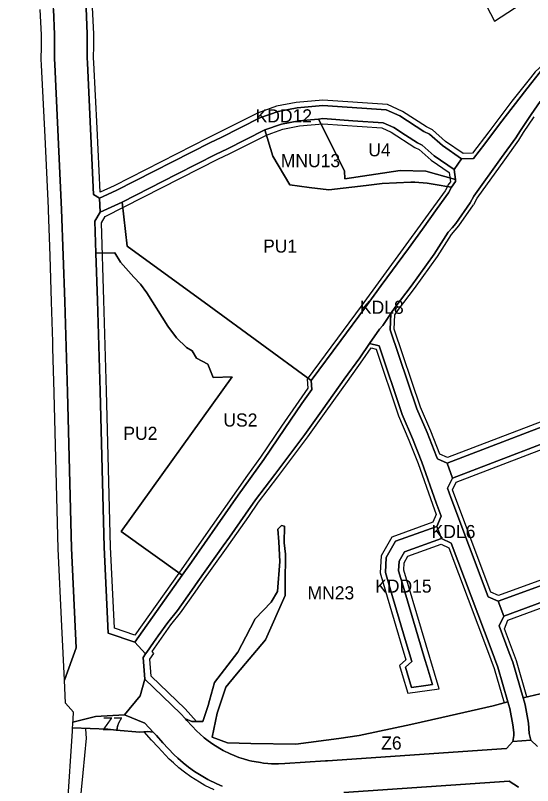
# Model space of a CAD drawing. Extents: x 7440055 to 7442242, y 5549003 to 5552256.
# Drawn here: x 7440536 to 7440932, y 5550092 to 5550680 of the extents above; entities that cross this region are included whole.
import ezdxf

# ---------------------------------------------------------------- set-up
doc = ezdxf.new("R2010")
doc.units = 0
for name, color, linetype in [('linie_rozgraniczajace', 7, 'Continuous'), ('linie_zabudowy_nieprzekraczalne', 7, 'Continuous'), ('oznaczenia_przeznaczen', 7, 'Continuous')]:
    doc.layers.add(name, color=color, linetype=linetype)

msp = doc.modelspace()

# ---------------------------------------------------------------- linework, layer by layer
at = {"layer": 'linie_rozgraniczajace'}
for points in [[(7440573.92, 5550172.69), (7440582.76, 5550197.27), (7440579.13, 5550273.35), (7440576.06, 5550392.67), (7440574.03, 5550461.9), (7440571.71, 5550531.98), (7440566.39, 5550642.67), (7440566.17, 5550647.16), (7440566.21, 5550665.57), (7440565.4, 5550685.1), (7440564.29, 5550711.77), (7440563.86, 5550722.35), (7440563.39, 5550733.5), (7440562.57, 5550746.25), (7440561.03, 5550769.99), (7440559.99, 5550785.92), (7440559.23, 5550801.45), (7440557.17, 5550854.15), (7440555.49, 5550871.65), (7440553.94, 5550886.18), (7440551.79, 5550907.38), (7440536.34, 5551228.21)], [(7440565.4, 5550685.1), (7440566.21, 5550665.57), (7440566.17, 5550647.16), (7440566.39, 5550642.67), (7440571.71, 5550531.98), (7440574.03, 5550461.9), (7440576.06, 5550392.67), (7440579.13, 5550273.35), (7440582.76, 5550197.27), (7440573.92, 5550172.69), (7440571.95, 5550214.02), (7440569.14, 5550272.98), (7440567.61, 5550332.35), (7440566.08, 5550391.72), (7440566.07, 5550392.39), (7440565.57, 5550409.22), (7440565.08, 5550426.06), (7440564.93, 5550431), (7440564.48, 5550446.3), (7440564.04, 5550461.59), (7440562.88, 5550496.59), (7440561.72, 5550531.58), (7440561.68, 5550532.37), (7440561.65, 5550533.16), (7440559.02, 5550587.67), (7440556.4, 5550642.19), (7440556.17, 5550646.93), (7440556.19, 5550656.15), (7440556.21, 5550665.37), (7440555.81, 5550675.03), (7440555.41, 5550684.69)], [(7440591.17, 5550647.75), (7440591.21, 5550666.06), (7440590.37, 5550686.14)], [(7440590.37, 5550686.14), (7440591.21, 5550666.06), (7440591.17, 5550647.75), (7440591.36, 5550643.88), (7440596.18, 5550543.57), (7440600.55, 5550540.64), (7440601.18, 5550529.91), (7440597.01, 5550523.23), (7440597.82, 5550498.78), (7440599.02, 5550462.68), (7440601.05, 5550393.36), (7440604.12, 5550274.26), (7440607.24, 5550208.62), (7440627.64, 5550201.8)], [(7440986.37, 5550682.63), (7440974.26, 5550670.64), (7440962.15, 5550658.65), (7440956.69, 5550654.35), (7440937.69, 5550637.36), (7440927.23, 5550624.19), (7440906.38, 5550597.1), (7440895.14, 5550582.1), (7440886.56, 5550571.01), (7440877.43, 5550570.75), (7440862.74, 5550580.86)], [(7440862.74, 5550580.86), (7440852.97, 5550589.55), (7440848.72, 5550591.65), (7440830.36, 5550603.47), (7440819.92, 5550608.19), (7440771.31, 5550611.47), (7440751.66, 5550609.72), (7440737.13, 5550606.98), (7440723.1, 5550602), (7440693.63, 5550587.11), (7440685.39, 5550583.26), (7440613.51, 5550546.64), (7440600.55, 5550540.64), (7440596.18, 5550543.57), (7440591.36, 5550643.88), (7440591.17, 5550647.75)], [(7440937.54, 5550614.43), (7440930.55, 5550604.54), (7440922.38, 5550592.41), (7440918.8, 5550586.69), (7440908.08, 5550571.82), (7440886.74, 5550542.25), (7440884.12, 5550537.22), (7440873.09, 5550521.44), (7440870.18, 5550518.07), (7440867.28, 5550514.71), (7440861.92, 5550506.27), (7440856.56, 5550497.84), (7440839.01, 5550473.46), (7440826.72, 5550457.37), (7440823.48, 5550452.67), (7440820.24, 5550447.97), (7440817.21, 5550443.41), (7440814.64, 5550440.77), (7440807.11, 5550429.83), (7440799.57, 5550418.9), (7440787.7, 5550402.48), (7440771.56, 5550379.89), (7440757.55, 5550360.16), (7440734.69, 5550329.81), (7440719.81, 5550310.29), (7440712.34, 5550299.45), (7440700.08, 5550281.97), (7440695.3, 5550275.32), (7440675.91, 5550248.1), (7440671.21, 5550241.5), (7440660.27, 5550225.91), (7440652.87, 5550216.76), (7440645.58, 5550206.45), (7440642.03, 5550201.42), (7440636.81, 5550194.03), (7440635.83, 5550192.65), (7440627.64, 5550201.8), (7440663.84, 5550252.75), (7440670.88, 5550262.67), (7440690.93, 5550291.4), (7440706.55, 5550313.81), (7440726.16, 5550341.14), (7440742.22, 5550364.95), (7440755.44, 5550383.92), (7440762.98, 5550394.73), (7440762.57, 5550401.52), (7440785.26, 5550431.95), (7440803.21, 5550456.45), (7440816.04, 5550473.95), (7440836.83, 5550502.27), (7440847.53, 5550516.98), (7440858.83, 5550532.84), (7440867.39, 5550544.81), (7440869.62, 5550549.11), (7440872.9, 5550553.35), (7440872.68, 5550555.07), (7440871.76, 5550562.52), (7440877.43, 5550570.75), (7440886.56, 5550571.01), (7440895.14, 5550582.1), (7440906.38, 5550597.1), (7440927.23, 5550624.19), (7440937.69, 5550637.36)], [(7440970.15, 5550377.98), (7440866.42, 5550338.29), (7440858.96, 5550341.75), (7440858.37, 5550343.45), (7440851.07, 5550361.74), (7440843.18, 5550379.93), (7440822.89, 5550440.17), (7440823.48, 5550452.67), (7440826.72, 5550457.37), (7440839.01, 5550473.46), (7440856.56, 5550497.84), (7440861.92, 5550506.27), (7440867.28, 5550514.71), (7440870.18, 5550518.07), (7440873.09, 5550521.44), (7440884.12, 5550537.22), (7440886.74, 5550542.25), (7440908.08, 5550571.82), (7440918.8, 5550586.69), (7440922.38, 5550592.41), (7440930.55, 5550604.54), (7440937.54, 5550614.43)], [(7440974.34, 5550366.74), (7440870.42, 5550326.97), (7440866.42, 5550338.29), (7440970.15, 5550377.98)], [(7440990.2, 5550263.91), (7440905.47, 5550232.9), (7440897.83, 5550236.24), (7440869.31, 5550312.08), (7440866.77, 5550319.38), (7440870.42, 5550326.97), (7440974.34, 5550366.74)], [(7440993.91, 5550252.48), (7440909.66, 5550221.66), (7440905.47, 5550232.9), (7440990.2, 5550263.91)], [(7440963.57, 5550168.27), (7440924.49, 5550159.2), (7440916.62, 5550186.44), (7440913.94, 5550193.48), (7440911.25, 5550200.53), (7440908.69, 5550207.34), (7440906.13, 5550214.15), (7440909.66, 5550221.66), (7440993.91, 5550252.48)], [(7440627.64, 5550201.8), (7440635.83, 5550192.65), (7440634.02, 5550190.08), (7440635.27, 5550173.32), (7440631.62, 5550160.64), (7440619.71, 5550146.25), (7440597.47, 5550145.03), (7440580.34, 5550140.54), (7440580.41, 5550141.53), (7440580.44, 5550142.16), (7440580.48, 5550142.79), (7440580.75, 5550148.12), (7440574.76, 5550155.07), (7440573.92, 5550172.69)], [(7440619.71, 5550146.25), (7440631.62, 5550160.64), (7440635.27, 5550173.32), (7440662.55, 5550147.18), (7440666.34, 5550143.04), (7440667.5, 5550141.78), (7440675.08, 5550133.7), (7440677.25, 5550131.67), (7440680.56, 5550128.75), (7440683.63, 5550126.33), (7440687.22, 5550123.79), (7440692.54, 5550120.46), (7440695.13, 5550118.97), (7440700.65, 5550116.38), (7440703.72, 5550115.04), (7440707.28, 5550113.71), (7440710.71, 5550112.58), (7440714.78, 5550111.45), (7440717.2, 5550110.87), (7440718.99, 5550110.48), (7440723.67, 5550109.67), (7440726.09, 5550109.35), (7440729.33, 5550109.05), (7440732.07, 5550108.87), (7440734.89, 5550108.78), (7440736.16, 5550108.77), (7440737.55, 5550108.79), (7440742.45, 5550108.99), (7440773.52, 5550111.1), (7440774.9, 5550111.19), (7440911.77, 5550120.46), (7440916.54, 5550125.84), (7440930.37, 5550126.73), (7440935.61, 5550122.08)], [(7440935.61, 5550122.08), (7440930.37, 5550126.73), (7440929.08, 5550132.04), (7440928.67, 5550139.92), (7440926.01, 5550153.93), (7440925.25, 5550156.57), (7440924.49, 5550159.2), (7440963.57, 5550168.27)], [(7440694.35, 5550091.85), (7440690.35, 5550093.6), (7440683.54, 5550096.79), (7440679.65, 5550099.04), (7440673.36, 5550102.97), (7440668.64, 5550106.31), (7440664.55, 5550109.55), (7440660.45, 5550113.16), (7440657.41, 5550116), (7440649.16, 5550124.78), (7440644.1, 5550130.31), (7440641.77, 5550132.87), (7440635.4, 5550139.84), (7440619.71, 5550146.25)], [(7440576.17, 5550076.23), (7440579.91, 5550133.83), (7440580.07, 5550136.34), (7440593.51, 5550135.79), (7440606.94, 5550135.23), (7440613.49, 5550134.57), (7440631.45, 5550132.87), (7440637.67, 5550133.41), (7440641.77, 5550132.87), (7440644.1, 5550130.31), (7440649.16, 5550124.78), (7440657.41, 5550116), (7440660.45, 5550113.16), (7440664.55, 5550109.55), (7440668.64, 5550106.31), (7440673.36, 5550102.97), (7440679.65, 5550099.04), (7440683.54, 5550096.79), (7440690.35, 5550093.6), (7440694.35, 5550091.85)], [(7440787.47, 5550086.98), (7440913.88, 5550095.55), (7440921.08, 5550091.06)], [(7440921.08, 5550091.06), (7440913.88, 5550095.55), (7440787.47, 5550086.98)]]:
    msp.add_lwpolyline(points, dxfattribs=at)
for points in [[(7440600.55, 5550540.64), (7440613.51, 5550546.64), (7440685.39, 5550583.26), (7440693.63, 5550587.11), (7440723.1, 5550602), (7440737.13, 5550606.98), (7440751.66, 5550609.72), (7440771.31, 5550611.47), (7440819.92, 5550608.19), (7440830.36, 5550603.47), (7440848.72, 5550591.65), (7440852.97, 5550589.55), (7440862.74, 5550580.86), (7440877.43, 5550570.75), (7440871.76, 5550562.52), (7440856.56, 5550572.98), (7440847.34, 5550581.18), (7440843.78, 5550582.93), (7440834.68, 5550588.8), (7440825.57, 5550594.67), (7440817.45, 5550598.33), (7440794.43, 5550599.89), (7440771.42, 5550601.45), (7440768.04, 5550601.14), (7440753.03, 5550599.8), (7440739.74, 5550597.3), (7440727.04, 5550592.79), (7440698, 5550578.12), (7440689.78, 5550574.27), (7440659.67, 5550558.93), (7440638.78, 5550548.29), (7440617.88, 5550537.64), (7440601.18, 5550529.91)], [(7440727.04, 5550592.79), (7440739.74, 5550597.3), (7440753.03, 5550599.8), (7440768.04, 5550601.14), (7440787.86, 5550561.53), (7440788.19, 5550555.47), (7440830.54, 5550561.81), (7440850.23, 5550561.22), (7440872.68, 5550555.07), (7440872.9, 5550553.35), (7440869.62, 5550549.11), (7440864.72, 5550549.93), (7440861.91, 5550550.4), (7440851.2, 5550552.18), (7440841.72, 5550553), (7440838.73, 5550552.97), (7440816.74, 5550552.01), (7440804.39, 5550550.42), (7440775.87, 5550546.97), (7440761.04, 5550548.96), (7440746.2, 5550550.95), (7440733.16, 5550572.76)], [(7440768.04, 5550601.14), (7440771.42, 5550601.45), (7440794.43, 5550599.89), (7440817.45, 5550598.33), (7440825.57, 5550594.67), (7440834.68, 5550588.8), (7440843.78, 5550582.93), (7440847.34, 5550581.18), (7440856.56, 5550572.98), (7440871.76, 5550562.52), (7440872.68, 5550555.07), (7440850.23, 5550561.22), (7440830.54, 5550561.81), (7440788.19, 5550555.47), (7440787.86, 5550561.53)], [(7440617.88, 5550537.64), (7440638.78, 5550548.29), (7440659.67, 5550558.93), (7440689.78, 5550574.27), (7440698, 5550578.12), (7440727.04, 5550592.79), (7440733.16, 5550572.76), (7440746.2, 5550550.95), (7440761.04, 5550548.96), (7440775.87, 5550546.97), (7440804.39, 5550550.42), (7440816.74, 5550552.01), (7440838.73, 5550552.97), (7440841.72, 5550553), (7440851.2, 5550552.18), (7440861.91, 5550550.4), (7440864.72, 5550549.93), (7440869.62, 5550549.11), (7440867.39, 5550544.81), (7440858.83, 5550532.84), (7440847.53, 5550516.98), (7440836.83, 5550502.27), (7440816.04, 5550473.95), (7440803.21, 5550456.45), (7440785.26, 5550431.95), (7440762.57, 5550401.52), (7440684.59, 5550458.38), (7440621.76, 5550504.17)], [(7440597.82, 5550498.78), (7440597.01, 5550523.23), (7440601.18, 5550529.91), (7440617.88, 5550537.64), (7440621.76, 5550504.17), (7440684.59, 5550458.38), (7440762.57, 5550401.52), (7440762.98, 5550394.73), (7440755.44, 5550383.92), (7440742.22, 5550364.95), (7440726.16, 5550341.14), (7440706.55, 5550313.81), (7440690.93, 5550291.4), (7440670.88, 5550262.67), (7440663.84, 5550252.75), (7440617.15, 5550286.17), (7440702.17, 5550404.37), (7440687.65, 5550403.78), (7440683.48, 5550413.89), (7440674.73, 5550418.57), (7440671.55, 5550424.11), (7440667.22, 5550426.69), (7440659.56, 5550433.94), (7440652.96, 5550443.02), (7440636.9, 5550468.37), (7440631.99, 5550474.94), (7440626.95, 5550480.51), (7440616.66, 5550491.91), (7440612.32, 5550499.03)], [(7440604.12, 5550274.26), (7440601.05, 5550393.36), (7440599.02, 5550462.68), (7440597.82, 5550498.78), (7440612.32, 5550499.03), (7440616.66, 5550491.91), (7440626.95, 5550480.51), (7440631.99, 5550474.94), (7440636.9, 5550468.37), (7440652.96, 5550443.02), (7440659.56, 5550433.94), (7440667.22, 5550426.69), (7440671.55, 5550424.11), (7440674.73, 5550418.57), (7440683.48, 5550413.89), (7440687.65, 5550403.78), (7440702.17, 5550404.37), (7440617.15, 5550286.17), (7440663.84, 5550252.75), (7440627.64, 5550201.8), (7440607.24, 5550208.62)], [(7440807.11, 5550429.83), (7440814.64, 5550440.77), (7440817.21, 5550443.41), (7440820.24, 5550447.97), (7440823.48, 5550452.67), (7440822.89, 5550440.17), (7440843.18, 5550379.93), (7440851.07, 5550361.74), (7440858.37, 5550343.45), (7440858.96, 5550341.75), (7440866.42, 5550338.29), (7440870.42, 5550326.97), (7440866.77, 5550319.38), (7440869.31, 5550312.08), (7440897.83, 5550236.24), (7440905.47, 5550232.9), (7440909.66, 5550221.66), (7440906.13, 5550214.15), (7440908.69, 5550207.34), (7440911.25, 5550200.53), (7440913.94, 5550193.48), (7440916.62, 5550186.44), (7440924.49, 5550159.2), (7440925.25, 5550156.57), (7440926.01, 5550153.93), (7440928.67, 5550139.92), (7440929.08, 5550132.04), (7440930.37, 5550126.73), (7440916.54, 5550125.84), (7440917.42, 5550130.49), (7440917.41, 5550132.69), (7440916.7, 5550138.65), (7440914.33, 5550151.14), (7440912.91, 5550156.03), (7440905.23, 5550182.63), (7440900.03, 5550196.28), (7440869.6, 5550277.23), (7440862.08, 5550280.74), (7440858.49, 5550290.07), (7440861.88, 5550297.77), (7440858.03, 5550307.99), (7440847.13, 5550339.24), (7440839.99, 5550357.13), (7440831.97, 5550375.62), (7440814.43, 5550427.93)], [(7440634.02, 5550190.08), (7440635.83, 5550192.65), (7440636.81, 5550194.03), (7440642.03, 5550201.42), (7440645.58, 5550206.45), (7440652.87, 5550216.76), (7440660.27, 5550225.91), (7440671.21, 5550241.5), (7440675.91, 5550248.1), (7440695.3, 5550275.32), (7440700.08, 5550281.97), (7440712.34, 5550299.45), (7440719.81, 5550310.29), (7440734.69, 5550329.81), (7440757.55, 5550360.16), (7440771.56, 5550379.89), (7440787.7, 5550402.48), (7440799.57, 5550418.9), (7440807.11, 5550429.83), (7440814.43, 5550427.93), (7440831.97, 5550375.62), (7440839.99, 5550357.13), (7440847.13, 5550339.24), (7440858.03, 5550307.99), (7440861.88, 5550297.77), (7440858.49, 5550290.07), (7440826.87, 5550278.7), (7440819.81, 5550266.32), (7440819.17, 5550254.99), (7440823.09, 5550241.65), (7440834.42, 5550203.77), (7440839.42, 5550186.97), (7440834.46, 5550182.59), (7440835.75, 5550178.25), (7440839.09, 5550167.15), (7440850.13, 5550168.64), (7440855.14, 5550169.32), (7440854.92, 5550170.06), (7440851.08, 5550182.84), (7440849.41, 5550188.45), (7440844, 5550206.63), (7440832.68, 5550244.49), (7440829.25, 5550256.15), (7440829.66, 5550263.41), (7440833.73, 5550270.54), (7440862.08, 5550280.74), (7440869.6, 5550277.23), (7440900.03, 5550196.28), (7440905.23, 5550182.63), (7440912.91, 5550156.03), (7440901.51, 5550153.02), (7440862.3, 5550144.12), (7440838.71, 5550138.78), (7440799.22, 5550130.45), (7440783.65, 5550128.21), (7440750.73, 5550123.68), (7440716.31, 5550124.36), (7440698.45, 5550124.72), (7440686.65, 5550129.11), (7440690.49, 5550147.56), (7440697.15, 5550167.33), (7440705.42, 5550177.19), (7440727.52, 5550203.5), (7440742.57, 5550237.34), (7440742.63, 5550246.57), (7440742.76, 5550268.88), (7440741.86, 5550277.58), (7440742.16, 5550290.35), (7440739.7, 5550290.82), (7440737.08, 5550287.89), (7440737.65, 5550278.18), (7440738.54, 5550263.18), (7440736.66, 5550240.37), (7440731.94, 5550232.25), (7440719.76, 5550219.41), (7440712.64, 5550205.87), (7440706.43, 5550194.05), (7440688.64, 5550170.92), (7440684.78, 5550157.24), (7440683.65, 5550153.24), (7440679.62, 5550141.19), (7440671.25, 5550141.19), (7440666.34, 5550143.04), (7440662.55, 5550147.18), (7440635.27, 5550173.32)], [(7440666.34, 5550143.04), (7440671.25, 5550141.19), (7440679.62, 5550141.19), (7440683.65, 5550153.24), (7440684.78, 5550157.24), (7440688.64, 5550170.92), (7440706.43, 5550194.05), (7440712.64, 5550205.87), (7440719.76, 5550219.41), (7440731.94, 5550232.25), (7440736.66, 5550240.37), (7440738.54, 5550263.18), (7440737.65, 5550278.18), (7440737.08, 5550287.89), (7440739.7, 5550290.82), (7440742.16, 5550290.35), (7440741.86, 5550277.58), (7440742.76, 5550268.88), (7440742.63, 5550246.57), (7440742.57, 5550237.34), (7440727.52, 5550203.5), (7440705.42, 5550177.19), (7440697.15, 5550167.33), (7440690.49, 5550147.56), (7440686.65, 5550129.11), (7440698.45, 5550124.72), (7440716.31, 5550124.36), (7440750.73, 5550123.68), (7440783.65, 5550128.21), (7440799.22, 5550130.45), (7440838.71, 5550138.78), (7440862.3, 5550144.12), (7440901.51, 5550153.02), (7440912.91, 5550156.03), (7440914.33, 5550151.14), (7440916.7, 5550138.65), (7440917.41, 5550132.69), (7440917.42, 5550130.49), (7440916.54, 5550125.84), (7440911.77, 5550120.46), (7440774.9, 5550111.19), (7440773.52, 5550111.1), (7440742.45, 5550108.99), (7440737.55, 5550108.79), (7440736.16, 5550108.77), (7440734.89, 5550108.78), (7440732.07, 5550108.87), (7440729.33, 5550109.05), (7440726.09, 5550109.35), (7440723.67, 5550109.67), (7440718.99, 5550110.48), (7440717.2, 5550110.87), (7440714.78, 5550111.45), (7440710.71, 5550112.58), (7440707.28, 5550113.71), (7440703.72, 5550115.04), (7440700.65, 5550116.38), (7440695.13, 5550118.97), (7440692.54, 5550120.46), (7440687.22, 5550123.79), (7440683.63, 5550126.33), (7440680.56, 5550128.75), (7440677.25, 5550131.67), (7440675.08, 5550133.7), (7440667.5, 5550141.78)], [(7440819.17, 5550254.99), (7440819.81, 5550266.32), (7440826.87, 5550278.7), (7440858.49, 5550290.07), (7440862.08, 5550280.74), (7440833.73, 5550270.54), (7440829.66, 5550263.41), (7440829.25, 5550256.15), (7440832.68, 5550244.49), (7440844, 5550206.63), (7440849.41, 5550188.45), (7440851.08, 5550182.84), (7440854.92, 5550170.06), (7440855.14, 5550169.32), (7440850.13, 5550168.64), (7440839.09, 5550167.15), (7440835.75, 5550178.25), (7440834.46, 5550182.59), (7440839.42, 5550186.97), (7440834.42, 5550203.77), (7440823.09, 5550241.65)], [(7440580.07, 5550136.34), (7440580.24, 5550138.93), (7440580.34, 5550140.54), (7440597.47, 5550145.03), (7440619.71, 5550146.25), (7440635.4, 5550139.84), (7440641.77, 5550132.87), (7440637.67, 5550133.41), (7440631.45, 5550132.87), (7440613.49, 5550134.57), (7440606.94, 5550135.23), (7440593.51, 5550135.79)]]:
    msp.add_lwpolyline(points, close=True, dxfattribs=at)
at = {"layer": 'linie_zabudowy_nieprzekraczalne'}
for points in [[(7440893.47, 5550693.61), (7440902.49, 5550675.88), (7440922.9, 5550689.1)], [(7440598.75, 5550594.27), (7440597.55, 5550619.2), (7440596.35, 5550644.12), (7440596.17, 5550647.86), (7440596.19, 5550657.01), (7440596.21, 5550666.16), (7440595.37, 5550686.34)], [(7440983.99, 5550684.49), (7440960.16, 5550660.9), (7440956.96, 5550658.38), (7440933.66, 5550637.11), (7440930.11, 5550632.64), (7440915.87, 5550614.78), (7440898.36, 5550591.41), (7440885.83, 5550574.99), (7440878.62, 5550574.79), (7440865.22, 5550584.01), (7440855.23, 5550592.9), (7440850.69, 5550595.14), (7440832.28, 5550607), (7440820.91, 5550612.13), (7440771.27, 5550615.49), (7440751.11, 5550613.68)], [(7440751.11, 5550613.68), (7440736.08, 5550610.86), (7440721.52, 5550605.68), (7440706.58, 5550598.13), (7440683.6, 5550586.84), (7440611.77, 5550550.23), (7440601.1, 5550545.3), (7440598.75, 5550594.12)], [(7440886.78, 5550535.83), (7440889.3, 5550540.67), (7440910.52, 5550570.07), (7440921.29, 5550585.01), (7440924.9, 5550590.77), (7440933.02, 5550602.83)], [(7440759.51, 5550402.43), (7440759.92, 5550395.59), (7440752.98, 5550385.64), (7440739.74, 5550366.65), (7440723.69, 5550342.86), (7440713.91, 5550329.21), (7440678.45, 5550278.76), (7440661.39, 5550254.48), (7440627.69, 5550207.05), (7440612.07, 5550212.27), (7440609.11, 5550274.44), (7440606.05, 5550393.49), (7440604.02, 5550462.84), (7440602.06, 5550521.88), (7440605, 5550526.59), (7440691.54, 5550570.68), (7440699.75, 5550574.52), (7440728.22, 5550588.91), (7440732.45, 5550590.47), (7440740.79, 5550593.43), (7440753.58, 5550595.83), (7440771.46, 5550597.43), (7440816.46, 5550594.39), (7440823.66, 5550591.14), (7440841.81, 5550579.45), (7440845.08, 5550577.83), (7440854.09, 5550569.82), (7440868.01, 5550560.24), (7440868.9, 5550553.08), (7440867, 5550550.7), (7440866.56, 5550549.74), (7440864.83, 5550546.39), (7440800.79, 5550458.22), (7440759.51, 5550402.43)], [(7440968.76, 5550381.73), (7440866.57, 5550342.63), (7440860.87, 5550345.27), (7440853.84, 5550362.9), (7440845.98, 5550381), (7440825.91, 5550440.59), (7440826.44, 5550451.67), (7440829.15, 5550455.61), (7440841.42, 5550471.67), (7440859.05, 5550496.16), (7440869.69, 5550512.91), (7440875.46, 5550519.59), (7440886.58, 5550535.5)], [(7440674.81, 5550141.19), (7440666.13, 5550150.68), (7440640.11, 5550175.61), (7440639.14, 5550188.66), (7440642.21, 5550193.02), (7440640.85, 5550194.55), (7440644.48, 5550199.69), (7440648.03, 5550204.72), (7440655.26, 5550214.95), (7440662.66, 5550224.1), (7440673.66, 5550239.77), (7440678.35, 5550246.36), (7440697.74, 5550273.57), (7440702.53, 5550280.23), (7440714.8, 5550297.74), (7440722.24, 5550308.52), (7440737.08, 5550328), (7440759.98, 5550358.39), (7440774.01, 5550378.15), (7440790.14, 5550400.73), (7440802.02, 5550417.17), (7440808.38, 5550426.4), (7440812.1, 5550425.44), (7440829.16, 5550374.54), (7440837.22, 5550355.98), (7440844.32, 5550338.19), (7440855.21, 5550306.97), (7440858.14, 5550299.19), (7440855.52, 5550293.25), (7440824.13, 5550281.97), (7440815.87, 5550267.49), (7440815.14, 5550254.52), (7440819.26, 5550240.51), (7440830.58, 5550202.63), (7440834.86, 5550188.28), (7440829.9, 5550183.9), (7440831.92, 5550177.1), (7440836.24, 5550162.73), (7440860.31, 5550165.99), (7440833.28, 5550256.61), (7440833.6, 5550262.24), (7440836.47, 5550267.28), (7440861.88, 5550276.41), (7440867.72, 5550273.69), (7440897.23, 5550195.22), (7440902.39, 5550181.68), (7440910.01, 5550155.26)], [(7440988.97, 5550267.71), (7440905.6, 5550237.21), (7440899.7, 5550239.79), (7440893.09, 5550257.35), (7440870.51, 5550317.94), (7440873.33, 5550323.8), (7440975.73, 5550362.99)], [(7440927.41, 5550159.88), (7440919.47, 5550187.39), (7440914.06, 5550201.59), (7440910.22, 5550211.8), (7440912.75, 5550218.53), (7440995.14, 5550248.68)], [(7440589.91, 5550135.23), (7440590.39, 5550128.47), (7440587.82, 5550101.87), (7440580.58, 5550026.69)], [(7440688.29, 5550089.04), (7440681.22, 5550092.35), (7440677.07, 5550094.75), (7440670.59, 5550098.81), (7440665.65, 5550102.31), (7440661.34, 5550105.71), (7440657.09, 5550109.45), (7440653.87, 5550112.46), (7440645.5, 5550121.39), (7440640.42, 5550126.94), (7440634.73, 5550133.16)]]:
    msp.add_lwpolyline(points, dxfattribs=at)

# ---------------------------------------------------------------- texts
at = {"layer": 'oznaczenia_przeznaczen'}
for s, p in [('KDD12', (7440720, 5550598.58)), ('U4', (7440806.13, 5550572.65)), ('MNU13', (7440739.25, 5550564.37)), ('PU1', (7440725.74, 5550499.14)), ('KDL8', (7440799.76, 5550452.41)), ('US2', (7440695.35, 5550366.3)), ('PU2', (7440618.89, 5550356.17)), ('KDL6', (7440854.58, 5550281.15)), ('KDD15', (7440811.42, 5550239.49)), ('MN23', (7440759.72, 5550234.36)), ('Z7', (7440602.86, 5550134.37)), ('Z6', (7440816.01, 5550119.69))]:
    msp.add_text(s, height=10, dxfattribs=at).set_placement(p)

doc.saveas('drawing.dxf')
